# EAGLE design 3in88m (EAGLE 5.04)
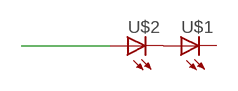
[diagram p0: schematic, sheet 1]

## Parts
U$1  LEDSMT1206  [1206]
U$2  LEDSMT1206  [1206]

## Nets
N$1: U$2.A
N$3: U$1.A U$2.C
Unconnected: U$1.C

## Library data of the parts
U$1 U$2 = led(2):LED: LED

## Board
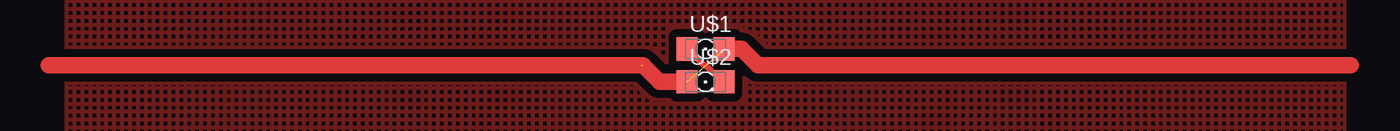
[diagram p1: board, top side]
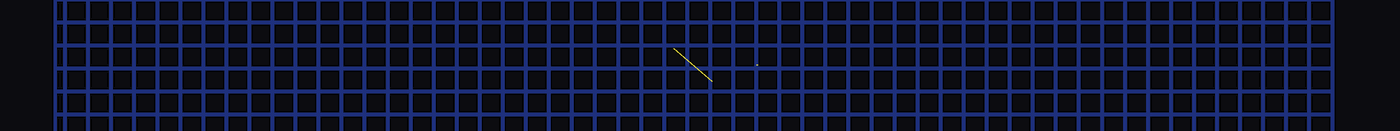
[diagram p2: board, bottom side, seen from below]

No outline drawn. Coordinates in mm, seen from the top.
Copper layers (1*16): Top 0.035mm / dielectric 1.5mm / Bottom 0.035mm
Design rules "default": minimum track width 10mil, minimum drill 24mil, track to track 8mil, track to pad 8mil, pad to pad 8mil, via to via 8mil, smd to smd 8mil, copper to edge 40mil, drill to drill 8mil, minimum pad ring 10mil, minimum via ring 8mil, stop-mask expansion 4mil, vias tented up to drill 0mil, thermal gap 10mil

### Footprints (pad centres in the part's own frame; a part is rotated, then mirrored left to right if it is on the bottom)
1206 = smd 1.6 x 1.803: A -1.422,0; C 1.422,0

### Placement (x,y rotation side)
U$1  49.28,13.97 0 top
U$2  49.28,11.43 0 top

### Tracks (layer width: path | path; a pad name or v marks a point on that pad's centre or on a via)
N$1  (2 unrouted)
  Top 1.27: 44.45,12.7 45.72,11.43 U$2.A | 99.06,12.7 53.34,12.7 52.07,13.97 50.8,13.97 | -1.4,12.7 44.32,12.7
N$2
  pour Top (isolate 0.61, hatched): 0,25.4 98.55,25.4 98.55,0 0,0
  pour Bottom (isolate 0.813, hatched): 0,25.4 98.55,25.4 98.55,0 0,0
N$3
  Top 0.406: U$1.A 47.88,13.97 49.15,12.7 49.28,12.7 50.04,11.94 50.19,11.94 U$2.C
